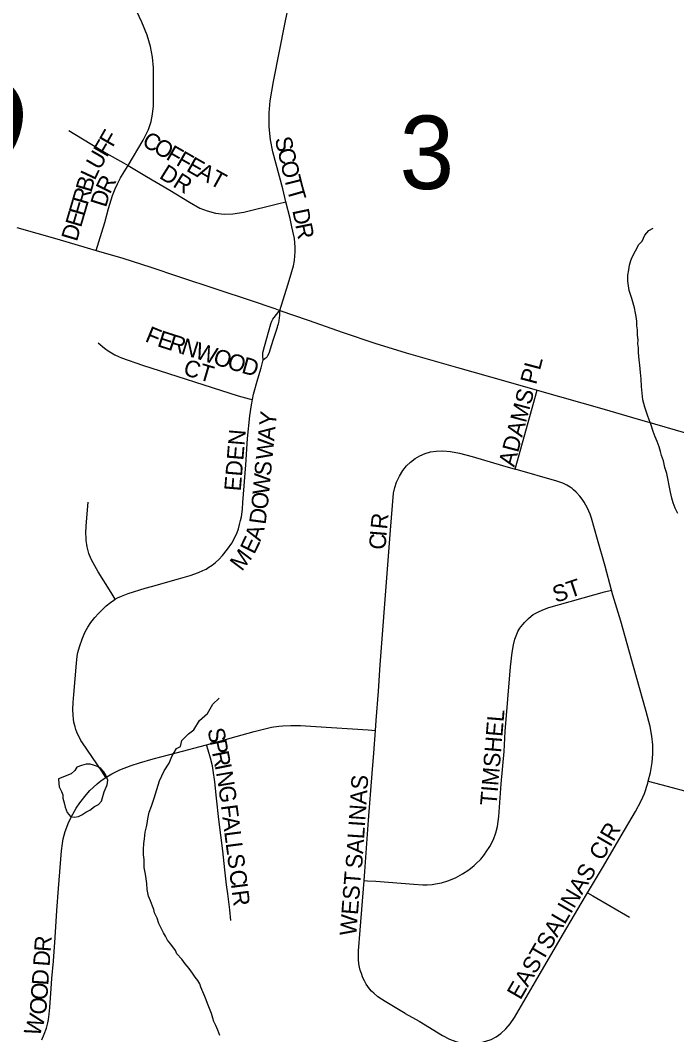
# Model space of a CAD drawing. Extents: x 1410790 to 1770854, y 448063 to 770588.
# Drawn here: x 1523114 to 1525089, y 605688 to 608740 of the extents above; entities that cross this region are included whole.
import ezdxf

# ---------------------------------------------------------------- set-up
doc = ezdxf.new("R2010")
doc.units = 0
for name, color, linetype in [('GM_X_County_Road', 7, 'Continuous'), ('GM_X_County_Road_Text', 7, 'Continuous'), ('GM_X_Minor_Lake', 7, 'Continuous'), ('GM_X_Minor_River', 7, 'Continuous'), ('GM_X_Section_Text', 7, 'Continuous'), ('GM_X_Township_Subdivision', 7, 'Continuous'), ('GM_X_Township_Subdivision_Text', 7, 'Continuous')]:
    doc.layers.add(name, color=color, linetype=linetype)

msp = doc.modelspace()

# ---------------------------------------------------------------- linework, layer by layer
at = {"layer": 'GM_X_County_Road'}
for points in [[(1523103.7, 608116.4), (1523223.7, 608082), (1523314.9, 608055.3), (1523342.4, 608047.1)], [(1523342.4, 608047.1), (1523421.7, 608023.5), (1523506, 607996.7), (1523590.2, 607968.9), (1523705.4, 607930.8), (1523804.9, 607897.3), (1523879.5, 607872.3), (1523894.8, 607866.9)], [(1523894.8, 607866.9), (1523980.1, 607837), (1524084.9, 607799.9), (1524180.4, 607768.2), (1524274.6, 607739.5), (1524429.1, 607694.6), (1524574.4, 607653.9), (1524668.9, 607626.9)], [(1524668.9, 607626.9), (1524870.8, 607569.4), (1524955.7, 607544.5), (1525021.9, 607525), (1525170.1, 607482.4), (1525220.5, 607467.9), (1525359.2, 607427.8), (1525478.7, 607392.7), (1525617.1, 607351.4), (1525654.9, 607340.3), (1525702.1, 607326.6), (1525726.2, 607319.5)]]:
    msp.add_lwpolyline(points, dxfattribs=at)
at = {"layer": 'GM_X_Minor_Lake'}
msp.add_lwpolyline([(1523228.8, 606457.3), (1523228.7, 606455.3), (1523230.2, 606433.3), (1523237.9, 606419), (1523241.7, 606408.9), (1523241.5, 606398.9), (1523245.2, 606384.8), (1523248.9, 606372.6), (1523254.5, 606356.4), (1523264.3, 606344.2), (1523276.2, 606341.9), (1523288.3, 606343.6), (1523298.5, 606349.4), (1523310.7, 606357.1), (1523322.8, 606362.8), (1523337.1, 606374.5), (1523349.2, 606380.2), (1523357.5, 606390.1), (1523366.1, 606417.9), (1523374.6, 606439.8), (1523376.9, 606453.8), (1523371.3, 606468), (1523365.5, 606478.1), (1523355.7, 606488.4), (1523345.8, 606494.7), (1523333.9, 606498.9), (1523323.9, 606501.2), (1523311.9, 606501.5), (1523297.8, 606497.8), (1523283.6, 606492.1), (1523277.4, 606482.3), (1523267.2, 606472.5), (1523228.8, 606457.3)], dxfattribs=at)
at = {"layer": 'GM_X_Minor_River'}
for points in [[(1525049.4, 607414.3), (1525043.6, 607430.4), (1525039.7, 607442.5), (1525035.8, 607456.6), (1525029.9, 607472.7), (1525024, 607486.8), (1525018.2, 607502.9), (1525012.3, 607521), (1525006.5, 607537.1), (1525000.6, 607551.2), (1524996.7, 607563.3), (1524992.8, 607575.3), (1524987, 607597.4), (1524985.1, 607617.5), (1524983.3, 607637.6), (1524981.5, 607659.7), (1524979.7, 607679.8), (1524977.9, 607701.8), (1524976, 607717.9), (1524974.2, 607740), (1524974.3, 607754), (1524972.4, 607766.1), (1524972.5, 607778.1), (1524970.7, 607792.2), (1524970.8, 607808.2), (1524968.9, 607820.2), (1524969.1, 607834.3), (1524967.2, 607848.3), (1524965.3, 607858.4), (1524961.4, 607874.5), (1524957.5, 607888.6), (1524953.6, 607902.6), (1524949.7, 607914.7), (1524945.8, 607926.8), (1524944, 607940.8), (1524942.1, 607954.9), (1524942.2, 607972.9), (1524944.4, 607989), (1524946.5, 608003), (1524950.6, 608017), (1524954.7, 608027), (1524975.1, 608064.9), (1524985.2, 608074.8), (1524993.4, 608092.8), (1525005.5, 608106.7), (1525017.6, 608114.6)], [(1525092.1, 607255.4), (1525084.2, 607271.6), (1525078.3, 607287.7), (1525074.5, 607301.7), (1525070.6, 607319.8), (1525059.1, 607376.1), (1525053.2, 607394.2), (1525049.4, 607414.3)], [(1523583.7, 606548.9), (1523595.8, 606554.8), (1523599.9, 606572.8), (1523620.1, 606592.7), (1523636.3, 606604.5), (1523652.5, 606632.5), (1523676.8, 606654.3), (1523693, 606682.2), (1523711.7, 606700.5)], [(1523714.2, 605685.3), (1523708.3, 605701.4), (1523702.4, 605715.5), (1523696.5, 605727.6), (1523692.6, 605737.6), (1523688.7, 605751.7), (1523684.8, 605761.8), (1523680.9, 605771.8), (1523677, 605781.9), (1523673.1, 605792), (1523669.2, 605802), (1523657.4, 605830.2), (1523653.5, 605840.3), (1523647.6, 605850.4), (1523639.6, 605860.5), (1523631.7, 605872.6), (1523621.8, 605886.8), (1523610, 605900.9), (1523600.1, 605915.1), (1523584.2, 605931.2), (1523580.3, 605941.3), (1523566.4, 605959.5), (1523556.5, 605971.7), (1523550.6, 605983.7), (1523544.7, 605993.8), (1523538.8, 606005.9), (1523530.9, 606022), (1523525.1, 606038.2), (1523517.2, 606054.3), (1523515.3, 606064.3), (1523511.4, 606074.4), (1523505.5, 606090.5), (1523499.6, 606104.6), (1523495.8, 606124.7), (1523494, 606142.8), (1523492.1, 606156.8), (1523490.2, 606170.9), (1523488.3, 606180.9), (1523486.4, 606191), (1523486.5, 606201), (1523486.6, 606215), (1523484.7, 606229.1), (1523484.8, 606245.1), (1523485, 606263.2), (1523487.1, 606277.2), (1523489.3, 606297.2), (1523493.5, 606313.2), (1523495.6, 606323.2), (1523497.7, 606337.2), (1523501.9, 606357.2), (1523508, 606375.2), (1523516.3, 606399.2), (1523524.5, 606425.2), (1523532.7, 606451.2), (1523547, 606481.1), (1523561.3, 606505), (1523569.5, 606525), (1523583.7, 606548.9)]]:
    msp.add_lwpolyline(points, dxfattribs=at)
at = {"layer": 'GM_X_Township_Subdivision'}
for points in [[(1523913, 608193.8), (1523903.3, 608232.9), (1523873.7, 608344), (1523866.8, 608379.5), (1523863, 608418.7), (1523862.5, 608461.3), (1523865.5, 608497.3), (1523875.3, 608555.6), (1523911.1, 608732.7), (1523941.3, 608884.1), (1523949.5, 608935.9), (1523952.7, 608978.5), (1523952, 609017.9), (1523947.5, 609060.3), (1523930.1, 609164), (1523913, 609271), (1523909, 609295.9)], [(1523438, 608303.2), (1523483.8, 608378.7), (1523499.1, 608410.7), (1523507.4, 608435), (1523511.9, 608456.9), (1523514.1, 608482.4), (1523514.6, 608596.9), (1523511.7, 608629.1), (1523505.5, 608660.8), (1523495.1, 608694.8), (1523479.4, 608734.1), (1523455.4, 608785.5), (1523437.9, 608827.4)], [(1523259.4, 608408.5), (1523323.6, 608369.2), (1523372.2, 608340.1), (1523424.2, 608311), (1523438, 608303.2)], [(1523342.4, 608047.1), (1523350.2, 608072.6), (1523368.1, 608131.6), (1523379.3, 608172.9), (1523391.4, 608212.8), (1523399.2, 608232.7), (1523406.4, 608247.6), (1523415.6, 608265.8), (1523426, 608283.4), (1523438, 608303.2)], [(1523438, 608303.2), (1523493.3, 608269.9), (1523563.8, 608228.2), (1523622.8, 608192.3), (1523654.3, 608174.7), (1523675.6, 608166.1), (1523701.1, 608159.7), (1523727.2, 608156.7), (1523753.4, 608157.1), (1523785.9, 608162.1), (1523887.9, 608187.5), (1523913, 608193.8)], [(1523894.8, 607866.9), (1523918.6, 607943.3), (1523925.9, 607966.5), (1523935.5, 608001.3), (1523938.4, 608016.6), (1523940.2, 608030.5), (1523940.8, 608042.8), (1523941.1, 608056.7), (1523938.8, 608082.8), (1523930.7, 608118), (1523925.4, 608143.7), (1523913, 608193.8)], [(1523844.9, 607718.4), (1523843.6, 607728.7), (1523843.5, 607734.6), (1523843.8, 607737.7), (1523844.7, 607743.1), (1523848.7, 607758.3), (1523868, 607825.9), (1523870.8, 607834.4), (1523873.3, 607839.9), (1523877.4, 607845.2), (1523884.4, 607854.4), (1523892, 607863.4), (1523893.8, 607865.6), (1523894.8, 607866.9)], [(1523844.9, 607718.4), (1523851, 607722.6), (1523854.8, 607725.5), (1523856.6, 607727.5), (1523858.8, 607731.1), (1523862.4, 607738.5), (1523874.3, 607777.4), (1523887.5, 607816.3), (1523888.9, 607821.2), (1523890.6, 607826.6), (1523891.7, 607830.8), (1523892.8, 607836.4), (1523894.4, 607852.5), (1523894.8, 607866.9)], [(1523348.4, 607768.9), (1523367.4, 607752.9), (1523378, 607745.5), (1523398, 607733.2), (1523409, 607727.9), (1523417.9, 607724.2), (1523480.9, 607701.6), (1523768.9, 607610.2), (1523802.7, 607600.9), (1523812.3, 607598.2)], [(1523812.3, 607598.2), (1523815.8, 607615), (1523828.3, 607661), (1523838.3, 607693.7), (1523844.9, 607718.4)], [(1524603.2, 607389.1), (1524668.9, 607626.9)], [(1523399.1, 606997.5), (1523406.5, 607001.8), (1523418.2, 607007.4), (1523438.2, 607014.9), (1523489, 607030.6), (1523508, 607036), (1523590, 607058.8), (1523624.7, 607068.9), (1523649.6, 607078), (1523663.2, 607083.9), (1523672.5, 607088.5), (1523681.3, 607094), (1523691, 607100.7), (1523700.9, 607108.4), (1523711.1, 607117.5), (1523721.9, 607128.9), (1523737.3, 607147.9), (1523750.1, 607166.4), (1523759.6, 607183.3), (1523765.9, 607198.1), (1523769.9, 607209.3), (1523773.5, 607222.5), (1523776.5, 607234.7), (1523778.9, 607246), (1523781.9, 607268.5), (1523783.4, 607288.7), (1523792.5, 607402.5), (1523797.7, 607481.2), (1523804.1, 607550), (1523809.1, 607582.7), (1523812.3, 607598.2)], [(1524182.4, 606603), (1524184.6, 606633.2), (1524191.2, 606721.5), (1524196.2, 606800.1), (1524218.6, 607088), (1524227.5, 607205.8), (1524237.1, 607317.1), (1524240.2, 607333.9), (1524245.7, 607350), (1524254.5, 607368.3), (1524265.2, 607385.5), (1524275.8, 607398.8), (1524288, 607410.6), (1524301.5, 607420.8), (1524316.1, 607429.5), (1524331.8, 607436.3), (1524348.2, 607440.9), (1524365, 607443.3), (1524385.3, 607443.9), (1524408.7, 607441.9), (1524434.9, 607437), (1524473.3, 607426.8), (1524564.5, 607400), (1524603.2, 607389.1)], [(1524892.6, 607025.1), (1524873.2, 607096.9), (1524850.9, 607177), (1524832.3, 607242), (1524828.4, 607253.6), (1524820.9, 607271.4), (1524810.7, 607289.4), (1524804.3, 607298.8), (1524797.2, 607308.2), (1524786.6, 607319.9), (1524778.4, 607327.1), (1524774, 607330.6), (1524768.3, 607334.7), (1524757.9, 607340.8), (1524746, 607346.7), (1524728.3, 607352.9), (1524603.2, 607389.1)], [(1523399.1, 606997.5), (1523386.7, 607017.7), (1523347.9, 607080.5), (1523332.6, 607106.8), (1523327.1, 607118), (1523320.2, 607134.9), (1523317.7, 607143.5), (1523315, 607155.1), (1523313.8, 607162.4), (1523312.3, 607174.6), (1523311.5, 607183.8), (1523311.3, 607195.5), (1523312.1, 607218.2), (1523318.2, 607289.9)], [(1524148.5, 606151.4), (1524158.2, 606150.8), (1524183.4, 606149.1), (1524298, 606140.2), (1524324.8, 606138.4), (1524337.6, 606138.6), (1524353.2, 606139.7), (1524363.4, 606141.1), (1524380.8, 606144.3), (1524400.2, 606150.2), (1524423.1, 606159.5), (1524444.2, 606171.3), (1524463.4, 606183.7), (1524479.4, 606196.9), (1524484.5, 606201.5), (1524499.1, 606216.1), (1524510.6, 606230.2), (1524515.9, 606237.4), (1524526.4, 606254.2), (1524537.7, 606275.3), (1524544.8, 606294.7), (1524549.3, 606314.2), (1524554.1, 606344), (1524560.8, 606442.4), (1524569.3, 606540.1), (1524573.2, 606599.9), (1524588.5, 606793.9), (1524593.7, 606837.7), (1524597.5, 606860.7), (1524601.8, 606877.6), (1524607.4, 606893.1), (1524610.8, 606900.4), (1524616.8, 606910.2), (1524620.2, 606915), (1524626.4, 606922.7), (1524630.7, 606927.6), (1524638.7, 606935.9), (1524642.9, 606939.9), (1524651.1, 606946.9), (1524657.4, 606951.4), (1524670.8, 606959.3), (1524686, 606965.8), (1524704.3, 606972.4), (1524872.1, 607019.6), (1524892.6, 607025.1)], [(1525003.3, 606449.9), (1525009.9, 606476.6), (1525014.7, 606506.1), (1525016.8, 606532.7), (1525016.7, 606559.4), (1525014.2, 606585.9), (1525008.9, 606615.3), (1524997.5, 606660.1), (1524958.6, 606795.7), (1524920.3, 606931.5), (1524896.6, 607010.1), (1524892.6, 607025.1)], [(1523371, 606461.3), (1523358.7, 606480), (1523300.8, 606565.5), (1523296.3, 606572.8), (1523293.6, 606577.7), (1523290, 606585), (1523283.8, 606598), (1523281, 606605.5), (1523278.4, 606614), (1523275.2, 606627.4), (1523273.8, 606636.8), (1523272.5, 606648.7), (1523271.7, 606665.9), (1523272.7, 606687), (1523274.5, 606711.6), (1523282.3, 606805.3), (1523284.9, 606826.5), (1523287, 606837.8), (1523291.5, 606854.9), (1523300.6, 606881), (1523309.2, 606899.3), (1523317, 606913.9), (1523326.2, 606927.8), (1523338.1, 606942.7), (1523348.5, 606954.9), (1523372.2, 606977.4), (1523384.6, 606988), (1523394.8, 606995), (1523399.1, 606997.5)], [(1523674.2, 606560.1), (1523703.1, 606567.8), (1523763.2, 606584.4), (1523817.6, 606599.5), (1523837.4, 606605.3), (1523869.5, 606612.5), (1523891.4, 606615.8), (1523904, 606617.1), (1523927.6, 606618.3), (1523956.9, 606618), (1524002.8, 606615.3), (1524160.7, 606604.5), (1524182.4, 606603)], [(1524148.5, 606151.4), (1524150.6, 606178.5), (1524161.3, 606333.1), (1524172, 606473.4), (1524177.3, 606535.1), (1524182.4, 606603)], [(1523371, 606461.3), (1523378.9, 606466.4), (1523389.1, 606472.4), (1523400.8, 606478.7), (1523413, 606484.6), (1523447, 606498), (1523472.2, 606505.6), (1523513.1, 606517.8), (1523582.7, 606535.8), (1523674.2, 606560.1)], [(1523747.5, 606031.2), (1523743.7, 606063.7), (1523737.7, 606111.4), (1523734.5, 606138.7), (1523729.2, 606183.3), (1523722.7, 606240.7), (1523711.4, 606334.9), (1523704, 606399.7), (1523699, 606448.8), (1523693.9, 606482.9), (1523691.6, 606496.1), (1523686.3, 606519.8), (1523679, 606544), (1523674.2, 606560.1)], [(1523178.2, 605671.9), (1523185.7, 605688.9), (1523192.5, 605707.7), (1523196.5, 605722.8), (1523198.8, 605732.8), (1523201, 605749.6), (1523202.8, 605768.9), (1523206.7, 605826.3), (1523208.9, 605856.4), (1523213.1, 605909), (1523218.3, 605980.2), (1523223.8, 606061.6), (1523228.6, 606127), (1523237.9, 606240.3), (1523240.4, 606262.9), (1523243, 606277), (1523248.6, 606298.5), (1523253.2, 606311.8), (1523257.8, 606323.2), (1523266.7, 606341.8), (1523282, 606368.9), (1523292.3, 606385.5), (1523311.6, 606409.5), (1523323.2, 606422.4), (1523332.7, 606431.7), (1523345.3, 606442.7), (1523356.1, 606451.1), (1523366.4, 606458.4), (1523371, 606461.3)], [(1524820.8, 606114.2), (1524868.7, 606195.1), (1524922.2, 606285.4), (1524964.9, 606359.4), (1524982.3, 606391.4), (1524991.5, 606412.8), (1525001.9, 606444.4), (1525003.3, 606449.9)], [(1525003.3, 606449.9), (1525021.7, 606445.2), (1525060.4, 606435.3), (1525127.2, 606417.5), (1525168.7, 606407.4)], [(1524271.4, 605751.3), (1524211.4, 605787.2), (1524189.7, 605801.8), (1524177.1, 605812.4), (1524170.9, 605818.3), (1524164.7, 605825.3), (1524154.4, 605840), (1524149, 605849.6), (1524144.8, 605858.4), (1524139.9, 605871.4), (1524136.7, 605881.6), (1524134.4, 605890.9), (1524132.6, 605900.3), (1524131.3, 605913.5), (1524131, 605929.6), (1524131.4, 605939.6), (1524136.8, 606002.1), (1524148.5, 606151.4)], [(1524271.4, 605751.3), (1524314.2, 605727.9), (1524384.5, 605685.5), (1524405.3, 605674.6), (1524424.2, 605667.4), (1524440.7, 605663.2), (1524457.5, 605661.3), (1524477.8, 605661.4), (1524498, 605663.6), (1524514.5, 605667.6), (1524530.5, 605673.6), (1524545.5, 605681.6), (1524559.4, 605691.4), (1524574.3, 605705.2), (1524587.5, 605720.5), (1524600.8, 605739.8), (1524664.3, 605847.3), (1524738.5, 605974.9), (1524801.9, 606082.2), (1524820.8, 606114.2)], [(1524820.8, 606114.2), (1524836.4, 606105.2), (1524946.6, 606040.9)]]:
    msp.add_lwpolyline(points, dxfattribs=at)

# ---------------------------------------------------------------- texts
at = {"layer": 'GM_X_County_Road_Text'}
msp.add_text('RD', height=300, rotation=343.854, dxfattribs=at).set_placement((1522532.6, 608410.1))
at = {"layer": 'GM_X_Section_Text'}
msp.add_text('3', height=221, rotation=0, dxfattribs=at).set_placement((1524254.9, 608231.9))
at = {"layer": 'GM_X_Township_Subdivision_Text'}
for s, rotation, p in [('F', 60.0583, (1523391.6, 608355.3)), ('F', 60.0583, (1523374.1, 608324.8)), ('C', 330.2401, (1523476.6, 608364.6)), ('O', 330.2274, (1523511, 608344.9)), ('S', 283.2742, (1523879, 608383.4)), ('U', 60.0613, (1523352.1, 608286.7)), ('F', 330.2364, (1523549.2, 608323.1)), ('C', 283.273, (1523887.1, 608349.1)), ('F', 330.2364, (1523579.8, 608305.6)), ('E', 330.2364, (1523610.3, 608288.1)), ('L', 64.9253, (1523337.7, 608255.8)), ('DR', 327.9903, (1523528.8, 608266.6)), ('A', 330.247, (1523640.9, 608270.6)), ('T', 330.9324, (1523679.6, 608248.5)), ('O', 283.2674, (1523896.2, 608310.6)), ('B', 73.631, (1523327.2, 608219.7)), ('R', 63.826, (1523383.3, 608214.7)), ('T', 283.9527, (1523906.5, 608267.1)), ('R', 73.6448, (1523316.1, 608181.7)), ('D', 72.8129, (1523371.1, 608174.6)), ('T', 286.1105, (1523915.5, 608231)), ('E', 73.6349, (1523306.2, 608147.9)), ('E', 73.6349, (1523296.2, 608114.1)), ('D', 281.7193, (1523931.9, 608167.6)), ('D', 73.6357, (1523283.9, 608071.9)), ('R', 281.4433, (1523940.8, 608124.6)), ('F', 337.6607, (1523486.3, 607774.6)), ('E', 342.2783, (1523523, 607759.7)), ('R', 342.379, (1523556.6, 607749)), ('N', 342.3702, (1523594.3, 607737)), ('W', 342.3901, (1523636.3, 607723.7)), ('O', 342.3702, (1523690.8, 607706.4)), ('CT', 343.6073, (1523601.2, 607673.6)), ('O', 342.954, (1523733.3, 607692.9)), ('D', 344.4885, (1523776.7, 607679.6)), ('ADAMS PL', 75.174, (1524600, 607393.6)), ('Y', 83.7479, (1523881.7, 607516.1)), ('EDEN', 85.2358, (1523776.9, 607321.6)), ('A', 84.4395, (1523877.5, 607472.4)), ('W', 84.527, (1523872, 607415.5)), ('S', 84.5167, (1523867.4, 607367.3)), ('W', 84.5073, (1523861.9, 607310.4)), ('O', 84.1183, (1523857.4, 607266.2)), ('D', 82.3998, (1523851.4, 607221)), ('R', 84.0768, (1524217.1, 607206.5)), ('A', 72.4692, (1523836.1, 607169.8)), ('C', 85.8555, (1524212.5, 607145.5)), ('I', 85.338, (1524215.4, 607184.8)), ('E', 63.9085, (1523817.5, 607130.7)), ('M', 52.9917, (1523780.3, 607079.6)), ('ST', 18.4393, (1524724.9, 606986.5)), ('TIMSHEL', 85.2373, (1524546.9, 606375.6)), ('S', 281.2724, (1523676.6, 606605.8)), ('P', 281.2868, (1523683.5, 606571.2)), ('R', 281.2671, (1523690.4, 606536.7)), ('I', 281.2816, (1523698.2, 606497.9)), ('N', 279.6743, (1523702.4, 606476.6)), ('SALINAS', 86.1231, (1524142.1, 606186)), ('G', 277.3961, (1523709.7, 606433.8)), ('F', 277.2877, (1523717, 606377.1)), ('A', 277.2852, (1523721.5, 606342.2)), ('CIR', 59.9285, (1524864.9, 606207.9)), ('L', 277.2857, (1523727.1, 606298.5)), ('L', 277.2923, (1523731.6, 606263.6)), ('S', 277.2877, (1523736, 606228.7)), ('C', 277.2887, (1523742.2, 606180.7)), ('SALINAS', 59.7413, (1524706.6, 605939.6)), ('WEST', 85.4859, (1524124.5, 605983.9)), ('I', 277.2903, (1523747.2, 606141.4)), ('R', 277.2822, (1523750, 606119.6)), ('R', 85.9206, (1523204.9, 605935.7)), ('D', 85.9097, (1523201.8, 605891.8)), ('EAST', 59.8577, (1524618.5, 605789.9)), ('D', 85.9165, (1523197.7, 605834.8)), ('O', 85.8715, (1523194.5, 605790.8)), ('O', 85.5673, (1523191.1, 605746.7)), ('W', 72.0836, (1523171, 605679.7))]:
    msp.add_text(s, height=50, rotation=rotation, dxfattribs=at).set_placement(p)

doc.saveas('drawing.dxf')
